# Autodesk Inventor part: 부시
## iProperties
IsCustomPart: 1
Created: 2009-02
Part Number: 부시
Material: 강, 연강
Description: 압력 맞춤 부시 - 머리 있는 유형
Document SubType Name: Modeling
Standard: ISO 4247
Designer: KYOUNG IL JANG
Standard Revision: 1판 1977-12-15
Standards Organization: ISO
Language: ko-KR
Size Designation: 15
Categories: <MemberInstance><Categories><Category DisplayName="기타 부품" InternalName="5aa15e00-363f-49f2-933f-16f664388e3f" Mnemonic="OTHER"><Category DisplayName="드릴 부싱" Int
Density: 1 g/cm^3
Author: KYOUNG IL JANG
